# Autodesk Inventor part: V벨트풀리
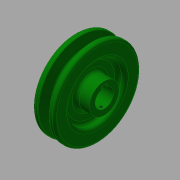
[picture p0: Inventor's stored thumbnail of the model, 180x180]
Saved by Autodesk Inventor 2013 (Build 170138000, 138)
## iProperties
Created: 2015-11
Part Number: V벨트풀리
Material: 강철, 탄소
Document SubType Name: Modeling
Designer: mduedu
Density: 1 g/cm^3
Author: mduedu
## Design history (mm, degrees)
sketch "스케치1"
  geometry: L1 (-9.5, 0)-(9.5, 0); L2 (0, 0)-(0, 37.7); L3 (-4.825, 37.7)-(-9.5, 37.7); L4 (-9.5, 37.7)-(-9.5, 0); L5 (0, 28.7)-(-2.074, 28.7); L6 (-2.074, 28.7)-(-4.825, 37.7); L7 (4.825, 37.7)-(9.5, 37.7); L8 (9.5, 37.7)-(9.5, 0); L9 (0, 28.7)-(2.074, 28.7); L10 (2.074, 28.7)-(4.825, 37.7); L11 (-9.5, 35)-(9.5, 35); 3 further points
  constraints: 22 end point, 7 point on line, 4 perpendicular, 3 symmetric about line, 1 coincident, 1 horizontal, 1 horizontal alignment, 1 midpoint, 1 vertical
  dimensions: "d0" = 19 distance of L1.start L1.end; "d2" = 75.4 diameter of L2.end L1 (derived); "d3" = 34 deg angle of L10 L6; "d4" = 6.3 distance between parallel lines of L11 L9; "d5" = 2.7 distance between parallel lines of L7 L11; "d6" = 8 distance of point (4, 35) point (-4, 35); "d7" = 70 diameter of L11 L1
revolve "회전1" sketch "스케치1" stored, may be unused: angle "d8" = 90 deg
sketch "스케치2"
  geometry: C1 r 24 at (0, 0); C2 r 13 at (0, 0); 1 further point
  constraints: 2 centre point, 2 coincident
  dimensions: "d9" = 48 diameter of C1; "d10" = 26 diameter of C2
extrude "돌출1" cut sketch "스케치2" distance "d11" = 6; taper "d12" = 0 deg
extrude "돌출3" join sketch "스케치2" distance "d37" = 6; taper "d38" = 0 deg
fillet "모깎기1" dims "d13" = 3
fillet "모깎기2" dims "d14" = 3
fillet "모깎기3" dims "d15" = 1, "d16" = 0.5, "d17" = 2
hole "구멍1" diameter "d20" = 16; stored, may be unused: countersink angle "d24" = 90 deg, drill point angle "d26" = 118 deg; dims "d21" = 6, "d22" = 4, "d23" = 2, "d25" = 8, "d53" = 10, "d54" = 10
sketch "스케치3"
  geometry: L1 (-2.5, 0)-(2.5, 0); L2 (2.5, 0)-(2.5, 10.3); L3 (2.5, 10.3)-(-2.5, 10.3); L4 (-2.5, 10.3)-(-2.5, 0); 2 further points
  constraints: 8 end point, 2 parallel, 1 coincident, 1 horizontal, 1 midpoint, 1 perpendicular
  dimensions: "d27" = 5 distance of L2.end L3.end; "d29" = 10.3 distance of L3.end L1.start
extrude "돌출2" cut sketch "스케치3" stored distance "d30" = 6; taper "d31" = 0 deg
node "작업 평면1"
sketch "스케치4"
  geometry: L1 (19, -27)-(19, 27) reference; 2 further points
  constraints: 1 horizontal alignment
  dimensions: "d52" = 22 distance from line of L1 point (-3, 0)
hole "구멍2" sketch "스케치4" at (-3, 0) diameter "d42" = 2.459; stored, may be unused: countersink angle "d46" = 90 deg, drill point angle "d48" = 118 deg; dims "d43" = 6, "d44" = 4, "d45" = 2, "d47" = 8
node "솔리드1"
mirror "대칭1"
